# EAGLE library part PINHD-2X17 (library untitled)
PIN HEADER
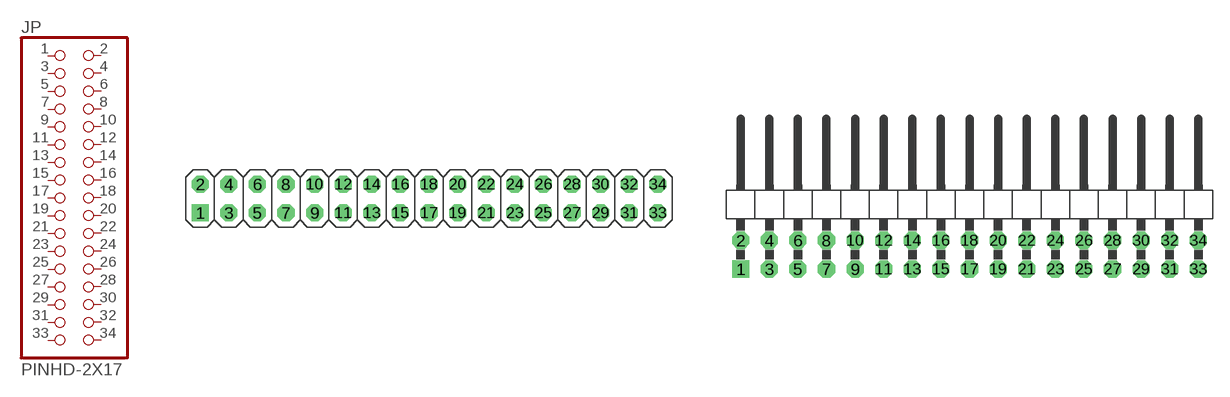
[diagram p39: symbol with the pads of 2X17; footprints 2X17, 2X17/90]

Designator prefix JP

## PINHD-2X17_2.54  [2X17]
1  1  pas
2  2  pas
3  3  pas
4  4  pas
5  5  pas
6  6  pas
7  7  pas
8  8  pas
9  9  pas
10  10  pas
11  11  pas
12  12  pas
13  13  pas
14  14  pas
15  15  pas
16  16  pas
17  17  pas
18  18  pas
19  19  pas
20  20  pas
21  21  pas
22  22  pas
23  23  pas
24  24  pas
25  25  pas
26  26  pas
27  27  pas
28  28  pas
29  29  pas
30  30  pas
31  31  pas
32  32  pas
33  33  pas
34  34  pas

## PINHD-2X17_2.54-90°  [2X17/90]
Pads as for 2X17

## PINHD-2X17_2.00  [2X17M]
Pads as for 2X17

## PINHD-2X17_2.54-SMD  [2X17SMD]
Pads as for 2X17

## PINHD-2X17_2.54-SMD-90°  [2X17SMD/90]
Pads as for 2X17

## Footprint 2X17 (pad centres in mm)
PIN HEADER - 2.54
drill 1.016 square: 1 -20.32,-1.27
drill 1.016 octagon: 2 -20.32,1.27; 3 -17.78,-1.27; 4 -17.78,1.27; 5 -15.24,-1.27; 6 -15.24,1.27; 7 -12.7,-1.27; 8 -12.7,1.27; 9 -10.16,-1.27; 10 -10.16,1.27; 11 -7.62,-1.27; 12 -7.62,1.27; 13 -5.08,-1.27; 14 -5.08,1.27; 15 -2.54,-1.27; 16 -2.54,1.27; 17 0,-1.27; 18 0,1.27; 19 2.54,-1.27; 20 2.54,1.27; 21 5.08,-1.27; 22 5.08,1.27; 23 7.62,-1.27; 24 7.62,1.27; 25 10.16,-1.27; 26 10.16,1.27; 27 12.7,-1.27; 28 12.7,1.27; 29 15.24,-1.27; 30 15.24,1.27; 31 17.78,-1.27; 32 17.78,1.27; 33 20.32,-1.27; 34 20.32,1.27

## Footprint 2X17/90 (pad centres in mm)
PIN HEADER - 2.54 90°
drill 1.016 square: 1 -20.32,-6.35
drill 1.016 octagon: 2 -20.32,-3.81; 3 -17.78,-6.35; 4 -17.78,-3.81; 5 -15.24,-6.35; 6 -15.24,-3.81; 7 -12.7,-6.35; 8 -12.7,-3.81; 9 -10.16,-6.35; 10 -10.16,-3.81; 11 -7.62,-6.35; 12 -7.62,-3.81; 13 -5.08,-6.35; 14 -5.08,-3.81; 15 -2.54,-6.35; 16 -2.54,-3.81; 17 0,-6.35; 18 0,-3.81; 19 2.54,-6.35; 20 2.54,-3.81; 21 5.08,-6.35; 22 5.08,-3.81; 23 7.62,-6.35; 24 7.62,-3.81; 25 10.16,-6.35; 26 10.16,-3.81; 27 12.7,-6.35; 28 12.7,-3.81; 29 15.24,-6.35; 30 15.24,-3.81; 31 17.78,-6.35; 32 17.78,-3.81; 33 20.32,-6.35; 34 20.32,-3.81

## Footprint 2X17M (pad centres in mm)
PIN HEADER - 2
drill 0.914 square: 1 -16,-1
drill 0.914 round: 2 -16,1; 3 -14,-1; 4 -14,1; 5 -12,-1; 6 -12,1; 7 -10,-1; 8 -10,1; 9 -8,-1; 10 -8,1; 11 -6,-1; 12 -6,1; 13 -4,-1; 14 -4,1; 15 -2,-1; 16 -2,1; 17 0,-1; 18 0,1; 19 2,-1; 20 2,1; 21 4,-1; 22 4,1; 23 6,-1; 24 6,1; 25 8,-1; 26 8,1; 27 10,-1; 28 10,1; 29 12,-1; 30 12,1; 31 14,-1; 32 14,1; 33 16,-1; 34 16,1

## Footprint 2X17SMD (pad centres in mm)
PIN HEADER - 2.54 SMD
smd 1.016 x 3.302: 1 -1.27,-3.81; 2 -1.27,1.27; 3 1.27,-3.81; 4 1.27,1.27; 5 3.81,-3.81; 6 3.81,1.27; 7 6.35,-3.81; 8 6.35,1.27; 9 8.89,-3.81; 10 8.89,1.27; 11 11.43,-3.81; 12 11.43,1.27; 13 13.97,-3.81; 14 13.97,1.27; 15 16.51,-3.81; 16 16.51,1.27; 17 19.05,-3.81; 18 19.05,1.27; 19 21.59,-3.81; 20 21.59,1.27; 21 24.13,-3.81; 22 24.13,1.27; 23 26.67,-3.81; 24 26.67,1.27; 25 29.21,-3.81; 26 29.21,1.27; 27 31.75,-3.81; 28 31.75,1.27; 29 34.29,-3.81; 30 34.29,1.27; 31 36.83,-3.81; 32 36.83,1.27; 33 39.37,-3.81; 34 39.37,1.27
